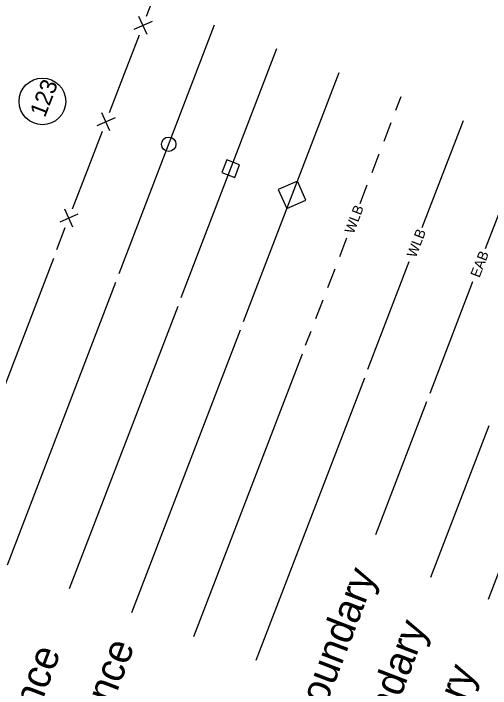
# Model space of a CAD drawing. Extents: x 1015221 to 1064345, y 619216 to 647967.
# Drawn here: x 1046459 to 1047582, y 626200 to 627789 of the extents above; entities that cross this region are included whole.
import ezdxf

# ---------------------------------------------------------------- set-up
doc = ezdxf.new("R2010")
doc.units = 0
doc.layers.add('Default', color=7, linetype='Continuous')

msp = doc.modelspace()

# ---------------------------------------------------------------- linework, layer by layer
at = {"layer": 'Default'}
for p, q in [((1046772.3, 627782.9), (1046786.1, 627818.8)), ((1046773.4, 627739.7), (1046754.4, 627782.3)), ((1046785.2, 627770.4), (1046742.6, 627751.5)), ((1046707.5, 627176.6), (1046932.6, 627762.5)), ((1046707.5, 627176.6), (1046932.6, 627762.5)), ((1046720.3, 627647.4), (1046755.5, 627739)), ((1046854, 627120.3), (1047079.1, 627706.3)), ((1046854, 627120.3), (1047079.1, 627706.3)), ((1046685.1, 627555.9), (1046720.3, 627647.4)), ((1047000.5, 627064), (1047225.6, 627650)), ((1047000.5, 627064), (1047225.6, 627650)), ((1047359.6, 627561.3), (1047372.1, 627593.7)), ((1046698, 627543.4), (1046655.4, 627524.4)), ((1046686.1, 627512.6), (1046667.2, 627555.2)), ((1047331.5, 627488.1), (1047348.4, 627532)), ((1047421.7, 627285.3), (1047518.5, 627537.4)), ((1046633, 627420.4), (1046668.2, 627511.9)), ((1047570.6, 627235.5), (1047664.9, 627481.2)), ((1047303.3, 627414.8), (1047320.2, 627458.8)), ((1046597.9, 627328.8), (1046633, 627420.4)), ((1047275.2, 627341.6), (1047292.1, 627385.5)), ((1046598.9, 627285.6), (1046580, 627328.2)), ((1046610.7, 627316.3), (1046568.1, 627297.4)), ((1046561, 627232.9), (1046581, 627284.9)), ((1047227.4, 627217.1), (1047244.2, 627261)), ((1046552.9, 627211.8), (1046144.6, 626149)), ((1047293.4, 626951.5), (1047390.7, 627204.7)), ((1047199.2, 627143.8), (1047216.1, 627187.8)), ((1046699.4, 627155.6), (1046443.8, 626490.2)), ((1047439.8, 626895.2), (1047540.7, 627157.9)), ((1047171.1, 627070.6), (1047188, 627114.5)), ((1046845.9, 627099.3), (1046590.3, 626434)), ((1046992.4, 627043), (1046736.8, 626377.7)), ((1047146.9, 627007.8), (1047159.8, 627041.3)), ((1047138.9, 626986.7), (1046883.2, 626321.4)), ((1047285.3, 626930.4), (1047029.7, 626265.1)), ((1047285.3, 626930.4), (1047029.7, 626265.1)), ((1047431.8, 626874.2), (1047311.7, 626561.6)), ((1047578.2, 626817.9), (1047441.1, 626460.9)), ((1047713.5, 626765.9), (1047576.4, 626409))]:
    msp.add_line(p, q, dxfattribs=at)
for points in [[(1046979.8, 627402.9), (1046991.3, 627433), (1046961.3, 627444.5), (1046949.8, 627414.5)], [(1047147.2, 627349.8), (1047127.4, 627394.4), (1047082.4, 627374.7), (1047102.6, 627329.9)]]:
    msp.add_lwpolyline(points, close=True, dxfattribs=at)
for centre, radius in [((1046527.1, 627582.1), 54.9), ((1046824.5, 627481.1), 16.9)]:
    msp.add_circle(centre, radius, dxfattribs=at)

# ---------------------------------------------------------------- texts
for s, height, p in [('123', 39.23, (1046532.8, 627542.3)), ('WLB', 23.54, (1047259.7, 627268.5)), ('WLB', 23.54, (1047406.2, 627212.2)), ('EAB', 23.54, (1047556.2, 627165.4)), ('Existing Endangered Animal Boundary', 68.654, (1046749.8, 624999.9)), ('Existing Endangered Plant Boundary', 68.654, (1046896.2, 624943.6)), ('Proposed Barbed Wire Fence', 68.654, (1046311.2, 625170.8)), ('Proposed Chain Link Fence', 68.654, (1046164.7, 625227.1)), ('Existing Historic Property Boundary', 68.654, (1047031.5, 624891.6))]:
    msp.add_text(s, height=height, rotation=68.983, dxfattribs=at).set_placement(p)

doc.saveas('drawing.dxf')
